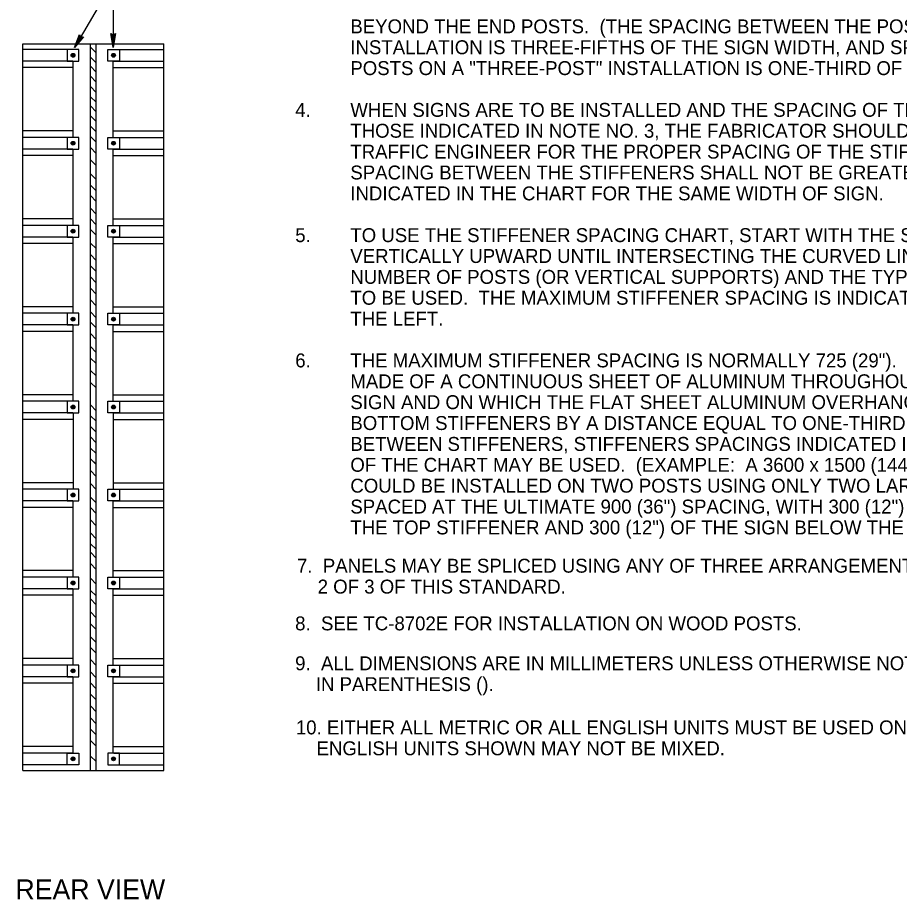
# Model space of a CAD drawing. Extents: x 650495 to 651400, y 297864 to 299646.
# Drawn here: x 651005.8 to 651195.9, y 299358.3 to 299548.4 of the extents above; entities that cross this region are included whole.
import ezdxf

# ---------------------------------------------------------------- set-up
doc = ezdxf.new("R2010")
doc.units = 0
doc.layers.add('2', color=7, linetype='Continuous')
doc.layers.add('3', color=7, linetype='Continuous')

# ---------------------------------------------------------------- blocks, each defined once
blk = doc.blocks.new('RARROW')
at = {"layer": '3'}
blk.add_lwpolyline([(-2.2695, 0.285), (-2.184875, 0.12075), (0, 0), (-2.2695, 0.285), (-2.38575, 0.384625), (0, 0), (-2.183125, -0.108), (-2.262875, -0.2705), (0, 0), (-2.38575, -0.379125), (-2.262875, -0.2705)], dxfattribs=at)

msp = doc.modelspace()

# ---------------------------------------------------------------- linework, layer by layer
at = {"layer": '2'}
for p, q in [((651026.41, 299556.11), (651018.09, 299541.93)), ((651026.41, 299556.11), (651026.4, 299541.95)), ((651006.95, 299386.13), (651006.95, 299542.76)), ((651006.95, 299542.76), (651037.34, 299542.76)), ((651021.52, 299386.13), (651021.52, 299542.76)), ((651022.78, 299386.13), (651022.78, 299542.76)), ((651037.34, 299386.13), (651037.34, 299542.76)), ((651017.72, 299541.53), (651006.95, 299541.53)), ((651019, 299541.53), (651016.48, 299541.53)), ((651016.48, 299541.53), (651016.48, 299539.01)), ((651019, 299539.01), (651019, 299541.53)), ((651022.78, 299540.79), (651021.52, 299542.05)), ((651025.29, 299539.01), (651025.29, 299541.53)), ((651025.29, 299541.53), (651027.81, 299541.53)), ((651026.58, 299541.53), (651037.34, 299541.53)), ((651027.81, 299541.53), (651027.81, 299539.01)), ((651017.72, 299539.01), (651006.95, 299539.01)), ((651016.48, 299539.01), (651019, 299539.01)), ((651017.84, 299522.57), (651017.84, 299539.01)), ((651022.78, 299538.66), (651021.52, 299539.83)), ((651027.81, 299539.01), (651025.29, 299539.01)), ((651026.45, 299522.57), (651026.45, 299539.01)), ((651026.58, 299539.01), (651037.34, 299539.01)), ((651017.84, 299537.61), (651006.95, 299537.61)), ((651022.78, 299536.63), (651021.52, 299537.89)), ((651026.45, 299537.61), (651037.34, 299537.61)), ((651022.78, 299534.5), (651021.52, 299535.76)), ((651022.78, 299532.28), (651021.52, 299533.53)), ((651022.78, 299532.28), (651021.52, 299533.53)), ((651022.78, 299530.15), (651021.52, 299531.31)), ((651022.78, 299528.11), (651021.52, 299529.37)), ((651022.78, 299525.98), (651021.52, 299527.24)), ((651017.84, 299523.97), (651006.95, 299523.97)), ((651022.78, 299523.76), (651021.52, 299525.02)), ((651026.45, 299523.97), (651037.34, 299523.97)), ((651017.72, 299522.57), (651006.95, 299522.57)), ((651019, 299522.57), (651016.48, 299522.57)), ((651016.48, 299522.57), (651016.48, 299520.05)), ((651019, 299520.05), (651019, 299522.57)), ((651022.78, 299521.53), (651021.52, 299522.79)), ((651025.29, 299520.05), (651025.29, 299522.57)), ((651025.29, 299522.57), (651027.81, 299522.57)), ((651026.58, 299522.57), (651037.34, 299522.57)), ((651027.81, 299522.57), (651027.81, 299520.05)), ((651017.72, 299520.05), (651006.95, 299520.05)), ((651016.48, 299520.05), (651019, 299520.05)), ((651017.84, 299503.61), (651017.84, 299520.05)), ((651022.78, 299519.11), (651021.52, 299520.37)), ((651027.81, 299520.05), (651025.29, 299520.05)), ((651026.45, 299503.61), (651026.45, 299520.05)), ((651026.58, 299520.05), (651037.34, 299520.05)), ((651017.84, 299518.66), (651006.95, 299518.66)), ((651022.78, 299516.5), (651021.52, 299517.76)), ((651026.45, 299518.66), (651037.34, 299518.66)), ((651022.78, 299513.5), (651021.52, 299514.75)), ((651022.78, 299511.08), (651021.52, 299512.24)), ((651022.78, 299508.75), (651021.52, 299510.01)), ((651022.78, 299506.04), (651021.52, 299507.3)), ((651017.84, 299505.01), (651006.95, 299505.01)), ((651022.78, 299503.72), (651021.52, 299504.98)), ((651026.45, 299505.01), (651037.34, 299505.01)), ((651017.72, 299503.61), (651006.95, 299503.61)), ((651019, 299503.61), (651016.48, 299503.61)), ((651016.48, 299503.61), (651016.48, 299501.1)), ((651019, 299501.1), (651019, 299503.61)), ((651022.78, 299501.49), (651021.52, 299502.75)), ((651025.29, 299501.1), (651025.29, 299503.61)), ((651025.29, 299503.61), (651027.81, 299503.61)), ((651026.58, 299503.61), (651037.34, 299503.61)), ((651027.81, 299503.61), (651027.81, 299501.1)), ((651017.72, 299501.1), (651006.95, 299501.1)), ((651016.48, 299501.1), (651019, 299501.1)), ((651017.84, 299484.66), (651017.84, 299501.1)), ((651027.81, 299501.1), (651025.29, 299501.1)), ((651026.45, 299484.66), (651026.45, 299501.1)), ((651026.58, 299501.1), (651037.34, 299501.1)), ((651017.84, 299499.7), (651006.95, 299499.7)), ((651022.78, 299498.59), (651021.52, 299499.75)), ((651026.45, 299499.7), (651037.34, 299499.7)), ((651022.78, 299496.07), (651021.52, 299497.33)), ((651022.78, 299493.65), (651021.52, 299494.91)), ((651022.78, 299491.23), (651021.52, 299492.49)), ((651022.78, 299488.81), (651021.52, 299490.07)), ((651022.78, 299486.3), (651021.52, 299487.55)), ((651017.84, 299486.06), (651006.95, 299486.06)), ((651026.45, 299486.06), (651037.34, 299486.06)), ((651017.72, 299484.66), (651006.95, 299484.66)), ((651019, 299484.66), (651016.48, 299484.66)), ((651016.48, 299484.66), (651016.48, 299482.14)), ((651019, 299482.14), (651019, 299484.66)), ((651022.78, 299483.68), (651021.52, 299484.94)), ((651025.29, 299482.14), (651025.29, 299484.66)), ((651025.29, 299484.66), (651027.81, 299484.66)), ((651026.58, 299484.66), (651037.34, 299484.66)), ((651027.81, 299484.66), (651027.81, 299482.14)), ((651017.72, 299482.14), (651006.95, 299482.14)), ((651016.48, 299482.14), (651019, 299482.14)), ((651017.84, 299465.7), (651017.84, 299482.14)), ((651022.78, 299481.55), (651021.52, 299482.71)), ((651027.81, 299482.14), (651025.29, 299482.14)), ((651026.45, 299465.7), (651026.45, 299482.14)), ((651026.58, 299482.14), (651037.34, 299482.14)), ((651017.84, 299480.75), (651006.95, 299480.75)), ((651022.78, 299479.04), (651021.52, 299480.29)), ((651026.45, 299480.75), (651037.34, 299480.75)), ((651022.78, 299476.23), (651021.52, 299477.49)), ((651022.78, 299473.81), (651021.52, 299474.97)), ((651022.78, 299471.19), (651021.52, 299472.36)), ((651022.78, 299468.58), (651021.52, 299469.74)), ((651017.84, 299467.1), (651006.95, 299467.1)), ((651026.45, 299467.1), (651037.34, 299467.1)), ((651017.72, 299465.7), (651006.95, 299465.7)), ((651019, 299465.7), (651016.48, 299465.7)), ((651016.48, 299465.7), (651016.48, 299463.19)), ((651019, 299463.19), (651019, 299465.7)), ((651022.78, 299463.64), (651021.52, 299464.9)), ((651025.29, 299463.19), (651025.29, 299465.7)), ((651025.29, 299465.7), (651027.81, 299465.7)), ((651026.58, 299465.7), (651037.34, 299465.7)), ((651027.81, 299465.7), (651027.81, 299463.19)), ((651017.72, 299463.19), (651006.95, 299463.19)), ((651016.48, 299463.19), (651019, 299463.19)), ((651017.84, 299463.19), (651017.84, 299446.75)), ((651022.78, 299461.42), (651021.52, 299462.58)), ((651027.81, 299463.19), (651025.29, 299463.19)), ((651026.45, 299463.19), (651026.45, 299446.75)), ((651026.58, 299463.19), (651037.34, 299463.19)), ((651017.84, 299461.79), (651006.95, 299461.79)), ((651026.45, 299461.79), (651037.34, 299461.79)), ((651022.78, 299459), (651021.52, 299460.26)), ((651022.78, 299456.77), (651021.52, 299458.03)), ((651022.78, 299454.45), (651021.52, 299455.61)), ((651022.68, 299452.13), (651021.52, 299453.29)), ((651022.78, 299452.13), (651021.52, 299453.29)), ((651022.78, 299449.51), (651021.52, 299450.77)), ((651017.84, 299448.15), (651006.95, 299448.15)), ((651022.78, 299446.7), (651021.52, 299447.96)), ((651026.45, 299448.15), (651037.34, 299448.15)), ((651017.72, 299446.75), (651006.95, 299446.75)), ((651019, 299446.75), (651016.48, 299446.75)), ((651016.48, 299446.75), (651016.48, 299444.23)), ((651019, 299444.23), (651019, 299446.75)), ((651025.29, 299444.23), (651025.29, 299446.75)), ((651025.29, 299446.75), (651027.81, 299446.75)), ((651026.58, 299446.75), (651037.34, 299446.75)), ((651027.81, 299446.75), (651027.81, 299444.23)), ((651017.72, 299444.23), (651006.95, 299444.23)), ((651016.48, 299444.23), (651019, 299444.23)), ((651017.84, 299427.79), (651017.84, 299444.23)), ((651022.78, 299443.8), (651021.52, 299445.06)), ((651027.81, 299444.23), (651025.29, 299444.23)), ((651026.45, 299427.79), (651026.45, 299444.23)), ((651026.58, 299444.23), (651037.34, 299444.23)), ((651017.84, 299442.83), (651006.95, 299442.83)), ((651022.78, 299441.48), (651021.61, 299442.74)), ((651026.45, 299442.83), (651037.34, 299442.83)), ((651022.78, 299438.86), (651021.52, 299440.12)), ((651022.78, 299436.06), (651021.52, 299437.31)), ((651022.78, 299433.83), (651021.52, 299434.99)), ((651022.78, 299431.89), (651021.52, 299433.15)), ((651022.78, 299429.47), (651021.52, 299430.73)), ((651017.84, 299429.19), (651006.95, 299429.19)), ((651026.45, 299429.19), (651037.34, 299429.19)), ((651017.72, 299427.79), (651006.95, 299427.79)), ((651019, 299427.79), (651016.48, 299427.79)), ((651016.48, 299427.79), (651016.48, 299425.28)), ((651019, 299425.28), (651019, 299427.79)), ((651022.78, 299426.28), (651021.52, 299427.54)), ((651025.29, 299425.28), (651025.29, 299427.79)), ((651025.29, 299427.79), (651027.81, 299427.79)), ((651026.58, 299427.79), (651037.34, 299427.79)), ((651027.81, 299427.79), (651027.81, 299425.28)), ((651017.72, 299425.28), (651006.95, 299425.28)), ((651016.48, 299425.28), (651019, 299425.28)), ((651017.84, 299408.84), (651017.84, 299425.28)), ((651022.78, 299423.76), (651021.52, 299424.92)), ((651027.81, 299425.28), (651025.29, 299425.28)), ((651026.45, 299408.84), (651026.45, 299425.28)), ((651026.58, 299425.28), (651037.34, 299425.28)), ((651017.84, 299423.88), (651006.95, 299423.88)), ((651022.78, 299421.83), (651021.52, 299423.09)), ((651026.45, 299423.88), (651037.34, 299423.88)), ((651022.78, 299419.02), (651021.52, 299420.28)), ((651022.78, 299416.5), (651021.52, 299417.76)), ((651022.78, 299413.7), (651021.52, 299414.95)), ((651022.78, 299411.37), (651021.52, 299412.63)), ((651017.84, 299410.24), (651006.95, 299410.24)), ((651022.78, 299408.76), (651021.52, 299410.02)), ((651026.45, 299410.24), (651037.34, 299410.24)), ((651017.72, 299408.84), (651006.95, 299408.84)), ((651019, 299408.84), (651016.48, 299408.84)), ((651016.48, 299408.84), (651016.48, 299406.32)), ((651019, 299406.32), (651019, 299408.84)), ((651022.68, 299406.15), (651021.52, 299407.4)), ((651025.29, 299406.32), (651025.29, 299408.84)), ((651025.29, 299408.84), (651027.81, 299408.84)), ((651026.58, 299408.84), (651037.34, 299408.84)), ((651027.81, 299408.84), (651027.81, 299406.32)), ((651017.72, 299406.32), (651006.95, 299406.32)), ((651016.48, 299406.32), (651019, 299406.32)), ((651017.84, 299389.88), (651017.84, 299406.32)), ((651027.81, 299406.32), (651025.29, 299406.32)), ((651026.45, 299389.88), (651026.45, 299406.32)), ((651026.58, 299406.32), (651037.34, 299406.32)), ((651017.84, 299404.92), (651006.95, 299404.92)), ((651022.68, 299403.82), (651021.52, 299404.98)), ((651026.45, 299404.92), (651037.34, 299404.92)), ((651022.78, 299401.31), (651021.52, 299402.56)), ((651022.78, 299398.79), (651021.61, 299399.95)), ((651022.78, 299396.17), (651021.52, 299397.43)), ((651022.68, 299393.85), (651021.52, 299395.01)), ((651022.78, 299391.33), (651021.52, 299392.59)), ((651017.84, 299391.28), (651006.95, 299391.28)), ((651026.45, 299391.28), (651037.34, 299391.28)), ((651017.72, 299389.88), (651006.95, 299389.88)), ((651016.48, 299389.88), (651019, 299389.88)), ((651016.48, 299387.37), (651016.48, 299389.88)), ((651017.74, 299389.88), (651017.74, 299389.88)), ((651019, 299389.88), (651019, 299387.37)), ((651022.78, 299388.04), (651021.52, 299389.21)), ((651027.81, 299389.88), (651025.29, 299389.88)), ((651025.29, 299389.88), (651025.29, 299387.37)), ((651026.55, 299389.88), (651026.55, 299389.88)), ((651026.58, 299389.88), (651037.34, 299389.88)), ((651027.81, 299387.37), (651027.81, 299389.88)), ((651017.72, 299387.37), (651006.95, 299387.37)), ((651019, 299387.37), (651016.48, 299387.37)), ((651025.29, 299387.37), (651027.81, 299387.37)), ((651026.58, 299387.37), (651037.34, 299387.37)), ((651006.95, 299386.13), (651037.34, 299386.13))]:
    msp.add_line(p, q, dxfattribs=at)
for points in [[(651017.65, 299539.98), (651017.55, 299540.27), (651017.55, 299540.46), (651017.74, 299540.56), (651017.94, 299540.46), (651018.03, 299540.36), (651018.03, 299540.07), (651017.94, 299539.98), (651017.74, 299539.98), (651017.65, 299540.27), (651017.65, 299540.36), (651017.65, 299540.46), (651017.74, 299540.46), (651017.84, 299540.36), (651017.94, 299540.27), (651017.94, 299540.07), (651017.84, 299540.17), (651017.74, 299540.36)], [(651026.65, 299539.98), (651026.75, 299540.27), (651026.75, 299540.46), (651026.55, 299540.56), (651026.36, 299540.46), (651026.26, 299540.36), (651026.26, 299540.07), (651026.36, 299539.98), (651026.55, 299539.98), (651026.65, 299540.27), (651026.65, 299540.36), (651026.65, 299540.46), (651026.55, 299540.46), (651026.45, 299540.36), (651026.36, 299540.27), (651026.36, 299540.07), (651026.45, 299540.17), (651026.55, 299540.36)], [(651017.65, 299521.02), (651017.55, 299521.31), (651017.55, 299521.51), (651017.74, 299521.6), (651017.94, 299521.51), (651018.03, 299521.41), (651018.03, 299521.12), (651017.94, 299521.02), (651017.74, 299521.02), (651017.65, 299521.31), (651017.65, 299521.41), (651017.65, 299521.51), (651017.74, 299521.51), (651017.84, 299521.41), (651017.94, 299521.31), (651017.94, 299521.12), (651017.84, 299521.22), (651017.74, 299521.41)], [(651026.65, 299521.02), (651026.75, 299521.31), (651026.75, 299521.51), (651026.55, 299521.6), (651026.36, 299521.51), (651026.26, 299521.41), (651026.26, 299521.12), (651026.36, 299521.02), (651026.55, 299521.02), (651026.65, 299521.31), (651026.65, 299521.41), (651026.65, 299521.51), (651026.55, 299521.51), (651026.45, 299521.41), (651026.36, 299521.31), (651026.36, 299521.12), (651026.45, 299521.22), (651026.55, 299521.41)], [(651017.65, 299502.07), (651017.55, 299502.36), (651017.55, 299502.55), (651017.74, 299502.65), (651017.94, 299502.55), (651018.03, 299502.45), (651018.03, 299502.16), (651017.94, 299502.07), (651017.74, 299502.07), (651017.65, 299502.36), (651017.65, 299502.45), (651017.65, 299502.55), (651017.74, 299502.55), (651017.84, 299502.45), (651017.94, 299502.36), (651017.94, 299502.16), (651017.84, 299502.26), (651017.74, 299502.45)], [(651026.65, 299502.07), (651026.75, 299502.36), (651026.75, 299502.55), (651026.55, 299502.65), (651026.36, 299502.55), (651026.26, 299502.45), (651026.26, 299502.16), (651026.36, 299502.07), (651026.55, 299502.07), (651026.65, 299502.36), (651026.65, 299502.45), (651026.65, 299502.55), (651026.55, 299502.55), (651026.45, 299502.45), (651026.36, 299502.36), (651026.36, 299502.16), (651026.45, 299502.26), (651026.55, 299502.45)], [(651017.65, 299483.11), (651017.55, 299483.4), (651017.55, 299483.59), (651017.74, 299483.69), (651017.94, 299483.59), (651018.03, 299483.5), (651018.03, 299483.21), (651017.94, 299483.11), (651017.74, 299483.11), (651017.65, 299483.4), (651017.65, 299483.5), (651017.65, 299483.59), (651017.74, 299483.59), (651017.84, 299483.5), (651017.94, 299483.4), (651017.94, 299483.21), (651017.84, 299483.3), (651017.74, 299483.5)], [(651026.65, 299483.11), (651026.75, 299483.4), (651026.75, 299483.59), (651026.55, 299483.69), (651026.36, 299483.59), (651026.26, 299483.5), (651026.26, 299483.21), (651026.36, 299483.11), (651026.55, 299483.11), (651026.65, 299483.4), (651026.65, 299483.5), (651026.65, 299483.59), (651026.55, 299483.59), (651026.45, 299483.5), (651026.36, 299483.4), (651026.36, 299483.21), (651026.45, 299483.3), (651026.55, 299483.5)], [(651017.65, 299464.16), (651017.55, 299464.45), (651017.55, 299464.64), (651017.74, 299464.74), (651017.94, 299464.64), (651018.03, 299464.54), (651018.03, 299464.25), (651017.94, 299464.16), (651017.74, 299464.16), (651017.65, 299464.45), (651017.65, 299464.54), (651017.65, 299464.64), (651017.74, 299464.64), (651017.84, 299464.54), (651017.94, 299464.45), (651017.94, 299464.25), (651017.84, 299464.35), (651017.74, 299464.54)], [(651026.65, 299464.16), (651026.75, 299464.45), (651026.75, 299464.64), (651026.55, 299464.74), (651026.36, 299464.64), (651026.26, 299464.54), (651026.26, 299464.25), (651026.36, 299464.16), (651026.55, 299464.16), (651026.65, 299464.45), (651026.65, 299464.54), (651026.65, 299464.64), (651026.55, 299464.64), (651026.45, 299464.54), (651026.36, 299464.45), (651026.36, 299464.25), (651026.45, 299464.35), (651026.55, 299464.54)], [(651017.65, 299445.2), (651017.55, 299445.49), (651017.55, 299445.68), (651017.74, 299445.78), (651017.94, 299445.68), (651018.03, 299445.59), (651018.03, 299445.3), (651017.94, 299445.2), (651017.74, 299445.2), (651017.65, 299445.49), (651017.65, 299445.59), (651017.65, 299445.68), (651017.74, 299445.68), (651017.84, 299445.59), (651017.94, 299445.49), (651017.94, 299445.3), (651017.84, 299445.39), (651017.74, 299445.59)], [(651026.65, 299445.2), (651026.75, 299445.49), (651026.75, 299445.68), (651026.55, 299445.78), (651026.36, 299445.68), (651026.26, 299445.59), (651026.26, 299445.3), (651026.36, 299445.2), (651026.55, 299445.2), (651026.65, 299445.49), (651026.65, 299445.59), (651026.65, 299445.68), (651026.55, 299445.68), (651026.45, 299445.59), (651026.36, 299445.49), (651026.36, 299445.3), (651026.45, 299445.39), (651026.55, 299445.59)], [(651017.65, 299426.24), (651017.55, 299426.54), (651017.55, 299426.73), (651017.74, 299426.83), (651017.94, 299426.73), (651018.03, 299426.63), (651018.03, 299426.34), (651017.94, 299426.24), (651017.74, 299426.24), (651017.65, 299426.54), (651017.65, 299426.63), (651017.65, 299426.73), (651017.74, 299426.73), (651017.84, 299426.63), (651017.94, 299426.54), (651017.94, 299426.34), (651017.84, 299426.44), (651017.74, 299426.63)], [(651026.65, 299426.24), (651026.75, 299426.54), (651026.75, 299426.73), (651026.55, 299426.83), (651026.36, 299426.73), (651026.26, 299426.63), (651026.26, 299426.34), (651026.36, 299426.24), (651026.55, 299426.24), (651026.65, 299426.54), (651026.65, 299426.63), (651026.65, 299426.73), (651026.55, 299426.73), (651026.45, 299426.63), (651026.36, 299426.54), (651026.36, 299426.34), (651026.45, 299426.44), (651026.55, 299426.63)], [(651017.65, 299407.29), (651017.55, 299407.58), (651017.55, 299407.77), (651017.74, 299407.87), (651017.94, 299407.77), (651018.03, 299407.68), (651018.03, 299407.39), (651017.94, 299407.29), (651017.74, 299407.29), (651017.65, 299407.58), (651017.65, 299407.68), (651017.65, 299407.77), (651017.74, 299407.77), (651017.84, 299407.68), (651017.94, 299407.58), (651017.94, 299407.39), (651017.84, 299407.48), (651017.74, 299407.68)], [(651026.65, 299407.29), (651026.75, 299407.58), (651026.75, 299407.77), (651026.55, 299407.87), (651026.36, 299407.77), (651026.26, 299407.68), (651026.26, 299407.39), (651026.36, 299407.29), (651026.55, 299407.29), (651026.65, 299407.58), (651026.65, 299407.68), (651026.65, 299407.77), (651026.55, 299407.77), (651026.45, 299407.68), (651026.36, 299407.58), (651026.36, 299407.39), (651026.45, 299407.48), (651026.55, 299407.68)], [(651017.65, 299388.91), (651017.55, 299388.62), (651017.55, 299388.43), (651017.74, 299388.33), (651017.94, 299388.43), (651018.03, 299388.53), (651018.03, 299388.82), (651017.94, 299388.91), (651017.74, 299388.91), (651017.65, 299388.62), (651017.65, 299388.53), (651017.65, 299388.43), (651017.74, 299388.43), (651017.84, 299388.53), (651017.94, 299388.62), (651017.94, 299388.82), (651017.84, 299388.72), (651017.74, 299388.53)], [(651026.65, 299388.91), (651026.75, 299388.62), (651026.75, 299388.43), (651026.55, 299388.33), (651026.36, 299388.43), (651026.26, 299388.53), (651026.26, 299388.82), (651026.36, 299388.91), (651026.55, 299388.91), (651026.65, 299388.62), (651026.65, 299388.53), (651026.65, 299388.43), (651026.55, 299388.43), (651026.45, 299388.53), (651026.36, 299388.62), (651026.36, 299388.82), (651026.45, 299388.72), (651026.55, 299388.53)]]:
    msp.add_lwpolyline(points, dxfattribs=at)
for centre in [(651017.78, 299540.27), (651026.51, 299540.27), (651017.78, 299521.31), (651026.51, 299521.31), (651017.78, 299502.36), (651026.51, 299502.36), (651017.78, 299483.4), (651026.51, 299483.4), (651017.78, 299464.45), (651026.51, 299464.45), (651017.78, 299445.49), (651026.51, 299445.49), (651017.78, 299426.53), (651026.51, 299426.53), (651017.78, 299407.58), (651026.51, 299407.58), (651017.78, 299388.63), (651026.51, 299388.63)]:
    msp.add_circle(centre, 0.407, dxfattribs=at)

# ---------------------------------------------------------------- block references
at = {"layer": '2', "yscale": 1.3092961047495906}
for p, xscale, rotation in [((651018.09, 299541.93), 1.257434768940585, -120.29357719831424), ((651026.4, 299541.95), 1.2574347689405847, -90.00000000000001)]:
    msp.add_blockref('RARROW', p, dxfattribs=dict(at, xscale=xscale, rotation=rotation))

# ---------------------------------------------------------------- texts
at = {"layer": '2'}
for s, height, p in [('BEYOND THE END POSTS.  (THE SPACING BETWEEN THE POSTS ON A "TWO-POST" ', 3, (651077.56, 299545)), ('INSTALLATION IS THREE-FIFTHS OF THE SIGN WIDTH, AND SPACING BETWEEN THE ', 3, (651077.56, 299540.5)), ('POSTS ON A "THREE-POST" INSTALLATION IS ONE-THIRD OF THE SIGN WIDTH.)', 3, (651077.56, 299536)), ('4.  ', 3, (651065.69, 299527)), ('WHEN SIGNS ARE TO BE INSTALLED AND THE SPACING OF THE POSTS IS OTHER THAN ', 3, (651077.56, 299527)), ('THOSE INDICATED IN NOTE NO. 3, THE FABRICATOR SHOULD CONSULT THE DISTRICT ', 3, (651077.56, 299522.5)), ('TRAFFIC ENGINEER FOR THE PROPER SPACING OF THE STIFFENERS.  HOWEVER, THE ', 3, (651077.56, 299518)), ('SPACING BETWEEN THE STIFFENERS SHALL NOT BE GREATER THAN THE SPACING ', 3, (651077.56, 299513.5)), ('INDICATED IN THE CHART FOR THE SAME WIDTH OF SIGN.', 3, (651077.56, 299509)), ('5.  ', 2.999, (651065.69, 299500)), ('TO USE THE STIFFENER SPACING CHART, START WITH THE SIGN WIDTH AND GO', 3, (651077.56, 299500)), ('VERTICALLY UPWARD UNTIL INTERSECTING THE CURVED LINE INDICATING THE PROPER', 3, (651077.56, 299495.5)), ('NUMBER OF POSTS (OR VERTICAL SUPPORTS) AND THE TYPE OF STIFFENER SECTION', 3, (651077.56, 299491)), ('TO BE USED.  THE MAXIMUM STIFFENER SPACING IS INDICATED HORIZONTALLY TO', 3, (651077.56, 299486.5)), ('THE LEFT.', 3, (651077.56, 299482)), ('6.  ', 2.999, (651065.69, 299473)), ('THE MAXIMUM STIFFENER SPACING IS NORMALLY 725 (29").  HOWEVER, FOR SIGNS', 3, (651077.56, 299473)), ('MADE OF A CONTINUOUS SHEET OF ALUMINUM THROUGHOUT THE HEIGHT OF THE ', 3, (651077.56, 299468.5)), ('SIGN AND ON WHICH THE FLAT SHEET ALUMINUM OVERHANGS BOTH THE TOP AND ', 3, (651077.56, 299464)), ('BOTTOM STIFFENERS BY A DISTANCE EQUAL TO ONE-THIRD OF THE SPACING', 3, (651077.56, 299459.5)), ('BETWEEN STIFFENERS, STIFFENERS SPACINGS INDICATED IN THE SHADED PORTION', 3, (651077.56, 299455)), ('OF THE CHART MAY BE USED.  (EXAMPLE:  A 3600 x 1500 (144" x 60") SIGN ', 3, (651077.56, 299450.5)), ('COULD BE INSTALLED ON TWO POSTS USING ONLY TWO LARGE SECTION STIFFENERS ', 3, (651077.56, 299446)), ('SPACED AT THE ULTIMATE 900 (36") SPACING, WITH 300 (12") OF THE SIGN ABOVE', 3, (651077.56, 299441.5)), ('THE TOP STIFFENER AND 300 (12") OF THE SIGN BELOW THE BOTTOM STIFFENER.)', 3, (651077.56, 299437)), ('7.  PANELS MAY BE SPLICED USING ANY OF THREE ARRANGEMENTS SHOWN ON SHEET', 3, (651066.06, 299428.75)), ('    2 OF 3 OF THIS STANDARD.', 3, (651066.06, 299424.25)), ('8.  SEE TC-8702E FOR INSTALLATION ON WOOD POSTS.', 3, (651065.66, 299416.32)), ('9.  ALL DIMENSIONS ARE IN MILLIMETERS UNLESS OTHERWISE NOTED.  ENGLISH UNITS', 3, (651065.66, 299407.72)), ('    IN PARENTHESIS ().', 3, (651065.66, 299403.22)), ('10. EITHER ALL METRIC OR ALL ENGLISH UNITS MUST BE USED ON PLANS.  METRIC AND', 3, (651065.82, 299393.9)), ('    ENGLISH UNITS SHOWN MAY NOT BE MIXED.', 3, (651065.82, 299389.4)), ('REAR VIEW', 4.3, (651005.37, 299358.34))]:
    msp.add_text(s, height=height, dxfattribs=at).set_placement(p)

doc.saveas('drawing.dxf')
